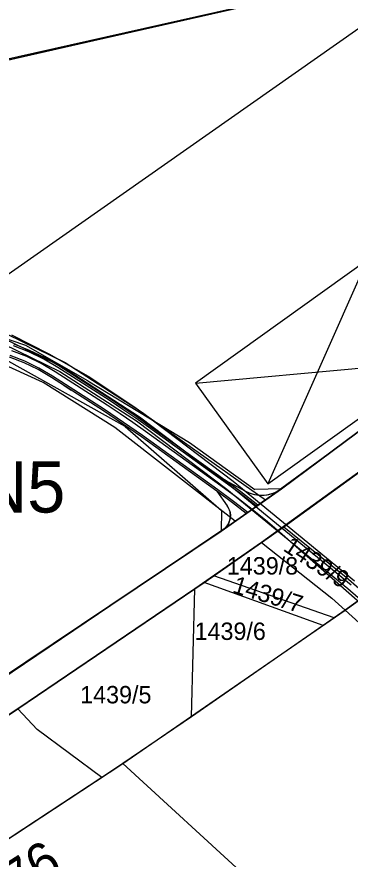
# Model space of a CAD drawing. Extents: x -510185 to -506993, y -1126306 to -1123642.
# Drawn here: x -508711.9 to -508614.4, y -1125228.7 to -1124982 of the extents above; entities that cross this region are included whole.
import ezdxf

# ---------------------------------------------------------------- set-up
doc = ezdxf.new("R2010")
doc.units = 0
for name, color, linetype in [('parcelni hranice', 7, 'Continuous'), ('popis cesty', 7, 'Continuous'), ('telefonica', 7, 'Continuous'), ('u_cesta20', 7, 'Continuous'), ('u_dalnice', 7, 'Continuous'), ('u_osa20', 7, 'Continuous'), ('u_popis', 7, 'Continuous'), ('u_stav dvur', 7, 'Continuous'), ('u_Telefonica', 7, 'Continuous'), ('u_vysadba', 7, 'Continuous'), ('ČEPS', 7, 'Continuous'), ('ˇ2', 7, 'Continuous')]:
    doc.layers.add(name, color=color, linetype=linetype)

msp = doc.modelspace()

# ---------------------------------------------------------------- linework, layer by layer
at = {"layer": 'parcelni hranice'}
for p, q in [((-508709.33, -1125078.25), (-508721.11, -1125074.28)), ((-508691.12, -1125088.59), (-508709.33, -1125078.25)), ((-508680.22, -1125102.02), (-508718.25, -1125080.76)), ((-508585.35, -1125083.77), (-508634.49, -1125120.22)), ((-508633.81, -1125131.37), (-508568.56, -1125084.09)), ((-508691.12, -1125088.59), (-508661.39, -1125106.67)), ((-508680.22, -1125102.02), (-508652.06, -1125126.63)), ((-508661.39, -1125106.67), (-508642.21, -1125120.44)), ((-508634.49, -1125120.22), (-508652.13, -1125132.63)), ((-508634.49, -1125120.22), (-508642.21, -1125120.44)), ((-508652.06, -1125126.63), (-508652.13, -1125132.63)), ((-508652.13, -1125132.63), (-508746.81, -1125196.18)), ((-508640.34, -1125135.94), (-508633.81, -1125131.37)), ((-508633.81, -1125131.37), (-508615.48, -1125146.13)), ((-508654.23, -1125145.68), (-508640.34, -1125135.94)), ((-508640.34, -1125135.94), (-508619.67, -1125152.26)), ((-508657.04, -1125147.63), (-508654.23, -1125145.68)), ((-508619.03, -1125158), (-508654.23, -1125145.68)), ((-508659.86, -1125149.57), (-508657.04, -1125147.63)), ((-508622.24, -1125160.26), (-508657.04, -1125147.63)), ((-508615.48, -1125146.13), (-508609.53, -1125151.29)), ((-508711.6, -1125184.7), (-508659.86, -1125149.57)), ((-508660.77, -1125187.02), (-508659.86, -1125149.57)), ((-508619.67, -1125152.26), (-508615.84, -1125155.75)), ((-508609.53, -1125151.29), (-508615.84, -1125155.75)), ((-508615.84, -1125155.75), (-508619.03, -1125158)), ((-508615.84, -1125155.75), (-508530.18, -1125233.9)), ((-508619.03, -1125158), (-508622.24, -1125160.26)), ((-508622.24, -1125160.26), (-508660.77, -1125187.02)), ((-508760.01, -1125216.39), (-508711.6, -1125184.7)), ((-508705.95, -1125190.73), (-508711.6, -1125184.7)), ((-508660.77, -1125187.02), (-508680.92, -1125200.66)), ((-508687.01, -1125204.78), (-508705.95, -1125190.73)), ((-508680.92, -1125200.66), (-508687.01, -1125204.78)), ((-508556.11, -1125315.05), (-508680.92, -1125200.66)), ((-508687.01, -1125204.78), (-508728.66, -1125232.15))]:
    msp.add_line(p, q, dxfattribs=at)
at = {"layer": 'telefonica'}
for points in [[(-508883.18, -1125073.45), (-508848.29, -1125060.66), (-508845.68, -1125060.26), (-508841.86, -1125061), (-508824.64, -1125072.31), (-508818.22, -1125076.69), (-508812.05, -1125079.64), (-508805.35, -1125080.64), (-508779.88, -1125079.41), (-508772.41, -1125078.59), (-508743.29, -1125072.5), (-508731.62, -1125071.61), (-508723.83, -1125072.19), (-508714.78, -1125074.96), (-508697.81, -1125083.24), (-508675.13, -1125097.89), (-508648.63, -1125118), (-508613.07, -1125147.17)], [(-508920.84, -1125089.73), (-508882.18, -1125076.27), (-508847.53, -1125063.58), (-508845.74, -1125063.3), (-508843.02, -1125063.84), (-508826.3, -1125074.81), (-508819.72, -1125079.29), (-508812.93, -1125082.54), (-508805.51, -1125083.66), (-508779.64, -1125082.41), (-508771.93, -1125081.55), (-508742.87, -1125075.48), (-508731.62, -1125074.61), (-508724.39, -1125075.15), (-508715.88, -1125077.76), (-508699.29, -1125085.86), (-508676.85, -1125100.35), (-508650.49, -1125120.36), (-508615.01, -1125149.47), (-508589.41, -1125171.82)]]:
    msp.add_lwpolyline(points, dxfattribs=at)
at = {"layer": 'u_cesta20'}
for p, q in [((-508698.1, -1125090), (-508696.04, -1125091.32)), ((-508650.98, -1125117.75), (-508645, -1125120.92)), ((-508653.35, -1125120.96), (-508650.32, -1125125.2))]:
    msp.add_line(p, q, dxfattribs=at)
for points in [[(-508641.78, -1125125.35), (-508646.65, -1125121.56), (-508651.29, -1125118.14), (-508673.43, -1125102.21), (-508677.13, -1125099.59), (-508680.86, -1125097.01), (-508684.63, -1125094.49), (-508688.43, -1125092.03), (-508699.92, -1125084.68), (-508704.06, -1125082.26), (-508708.4, -1125080.14), (-508712.88, -1125078.37)], [(-508641.35, -1125125.05), (-508646.35, -1125121.16), (-508651, -1125117.73), (-508673.14, -1125101.8), (-508676.84, -1125099.18), (-508680.58, -1125096.6), (-508684.36, -1125094.07), (-508688.16, -1125091.61), (-508699.66, -1125084.25), (-508703.82, -1125081.82), (-508708.2, -1125079.69), (-508712.72, -1125077.9)], [(-508644.77, -1125127.45), (-508648.77, -1125124.35), (-508653.35, -1125120.96), (-508675.47, -1125105.05), (-508679.13, -1125102.45), (-508682.83, -1125099.91), (-508686.56, -1125097.42), (-508690.33, -1125094.97), (-508701.75, -1125087.67), (-508705.71, -1125085.34), (-508709.81, -1125083.35), (-508714.04, -1125081.68)], [(-508644.34, -1125127.15), (-508648.47, -1125123.95), (-508653.06, -1125120.56), (-508675.18, -1125104.65), (-508678.85, -1125102.04), (-508682.55, -1125099.5), (-508686.28, -1125097), (-508690.06, -1125094.55), (-508701.49, -1125087.24), (-508705.48, -1125084.9), (-508709.61, -1125082.89), (-508713.88, -1125081.2)]]:
    msp.add_lwpolyline(points, dxfattribs=at)
for points in [[(-508650.98, -1125117.75), (-508645, -1125120.92), (-508643.93, -1125121.44), (-508642.78, -1125121.77), (-508641.46, -1125122.04), (-508640.41, -1125122.1), (-508639.56, -1125122.06), (-508638.64, -1125121.96), (-508637.53, -1125121.71), (-508636.32, -1125121.27), (-508635.46, -1125120.84), (-508634.49, -1125120.22), (-508641.35, -1125125.05), (-508646.35, -1125121.16)], [(-508653.35, -1125120.96), (-508650.32, -1125125.2), (-508649.54, -1125126.75), (-508649.38, -1125127.82), (-508649.46, -1125128.94), (-508649.92, -1125130.49), (-508650.61, -1125131.35), (-508651.51, -1125132.2), (-508644.77, -1125127.45), (-508648.77, -1125124.35)]]:
    msp.add_lwpolyline(points, close=True, dxfattribs=at)
for centre, radius, start, end in [((-508640.31, -1125112.09), 10, 242.0215, 306.5665), ((-508654.39, -1125128.11), 5, 305.127, 35.5821)]:
    msp.add_arc(centre, radius, start, end, dxfattribs=at)
at = {"layer": 'u_dalnice'}
for points in [[(-508307.98, -1124853.09), (-508351.15, -1124903.3), (-508395.31, -1124933.42), (-508430.84, -1124957.09), (-508470.01, -1124969.39), (-508498.1, -1124985.49), (-508504.09, -1124992.25), (-508507.8, -1125000.91), (-508507.87, -1125010.02), (-508504.83, -1125020.2), (-508497.14, -1125029.69), (-508568.56, -1125084.09), (-508640.34, -1125135.94), (-508659.86, -1125149.57), (-508711.6, -1125184.7), (-508760.01, -1125216.39), (-508781.13, -1125229.9), (-508797.28, -1125240.07), (-508802.36, -1125243.25), (-508808.34, -1125246.99), (-508884.57, -1125292.95)], [(-508883.7, -1125327.34), (-508849.68, -1125307.43), (-508793.17, -1125273.22), (-508768.24, -1125257.59), (-508728.66, -1125232.15), (-508680.92, -1125200.66), (-508615.84, -1125155.75), (-508609.53, -1125151.29), (-508577.81, -1125128.66), (-508544.87, -1125104.09), (-508479.09, -1125054.05), (-508464.05, -1125074.51), (-508457.81, -1125079.15), (-508450.36, -1125080.3), (-508443.41, -1125079.08), (-508435.52, -1125073.29), (-508420.42, -1125058.52), (-508416.68, -1125054.97), (-508374.92, -1125015.28), (-508354.65, -1124976.88), (-508350.21, -1124971.95), (-508276.53, -1124888.42)], [(-508560.91, -1124929.62), (-508567.97, -1124954.59), (-508793.68, -1125112.97), (-509052.14, -1125265.43), (-509087.92, -1125269.66)]]:
    msp.add_lwpolyline(points, dxfattribs=at)
at = {"layer": 'u_osa20'}
msp.add_lwpolyline([(-508527.62, -1125227.51), (-508634.24, -1125133.64), (-508638.59, -1125129.9), (-508643.03, -1125126.27), (-508647.56, -1125122.76), (-508652.17, -1125119.35), (-508674.3, -1125103.43), (-508677.99, -1125100.82), (-508681.71, -1125098.25), (-508685.46, -1125095.74), (-508689.25, -1125093.29), (-508700.71, -1125085.96), (-508704.77, -1125083.58), (-508709, -1125081.52), (-508713.38, -1125079.79)], dxfattribs=at)
at = {"layer": 'u_stav dvur'}
for p, q in [((-508609.4, -1125053.25), (-508638.47, -1125118.8)), ((-508659.65, -1125089.26), (-508588.23, -1125082.79))]:
    msp.add_line(p, q, dxfattribs=at)
msp.add_lwpolyline([(-508638.47, -1125118.8), (-508588.23, -1125082.79), (-508609.4, -1125053.25), (-508659.65, -1125089.26)], close=True, dxfattribs=at)
at = {"layer": 'u_Telefonica'}
msp.add_lwpolyline([(-508921.34, -1125088.32), (-508882.68, -1125074.86), (-508847.91, -1125062.12), (-508845.71, -1125061.78), (-508842.44, -1125062.42), (-508825.47, -1125073.56), (-508818.97, -1125077.99), (-508812.49, -1125081.09), (-508805.43, -1125082.15), (-508779.76, -1125080.91), (-508772.17, -1125080.07), (-508743.08, -1125073.99), (-508731.62, -1125073.11), (-508724.11, -1125073.67), (-508715.33, -1125076.36), (-508698.55, -1125084.55), (-508675.99, -1125099.12), (-508649.56, -1125119.18), (-508614.04, -1125148.32)], dxfattribs=at)
msp.add_lwpolyline([(-508921.34, -1125088.32), (-508882.68, -1125074.86), (-508847.91, -1125062.12), (-508845.71, -1125061.78), (-508842.44, -1125062.42), (-508825.47, -1125073.56), (-508818.97, -1125077.99), (-508812.49, -1125081.09), (-508805.43, -1125082.15), (-508779.76, -1125080.91), (-508772.17, -1125080.07), (-508743.08, -1125073.99), (-508731.62, -1125073.11), (-508724.11, -1125073.67), (-508715.33, -1125076.36), (-508698.55, -1125084.55), (-508675.99, -1125099.12), (-508649.56, -1125119.18), (-508614.04, -1125148.32)], dxfattribs=at)
msp.add_lwpolyline([(-508921.34, -1125088.32), (-508882.68, -1125074.86), (-508847.91, -1125062.12), (-508845.71, -1125061.78), (-508842.44, -1125062.42), (-508825.47, -1125073.56), (-508818.97, -1125077.99), (-508812.49, -1125081.09), (-508805.43, -1125082.15), (-508779.76, -1125080.91), (-508772.17, -1125080.07), (-508743.08, -1125073.99), (-508731.62, -1125073.11), (-508724.11, -1125073.67), (-508715.33, -1125076.36), (-508698.55, -1125084.55), (-508675.99, -1125099.12), (-508649.56, -1125119.18), (-508614.04, -1125148.32)], dxfattribs=at)
msp.add_lwpolyline([(-508921.34, -1125088.32), (-508882.68, -1125074.86), (-508847.91, -1125062.12), (-508845.71, -1125061.78), (-508842.44, -1125062.42), (-508825.47, -1125073.56), (-508818.97, -1125077.99), (-508812.49, -1125081.09), (-508805.43, -1125082.15), (-508779.76, -1125080.91), (-508772.17, -1125080.07), (-508743.08, -1125073.99), (-508731.62, -1125073.11), (-508724.11, -1125073.67), (-508715.33, -1125076.36), (-508698.55, -1125084.55), (-508675.99, -1125099.12), (-508649.56, -1125119.18), (-508614.04, -1125148.32)], dxfattribs=at)
at = {"layer": 'u_vysadba'}
for p, q in [((-508634.49, -1125120.22), (-508585.35, -1125083.77)), ((-508652.13, -1125132.63), (-508634.49, -1125120.22)), ((-508746.81, -1125196.18), (-508652.13, -1125132.63))]:
    msp.add_line(p, q, dxfattribs=at)
for points in [[(-508573.27, -1124905.18), (-508693.43, -1124932.21), (-508701.3, -1124937.12), (-508707.69, -1124938.84), (-508716.04, -1124937.62), (-508729.56, -1124953.83), (-508713.83, -1124975.46), (-508717.76, -1124995.36), (-508574.5, -1124962.68)], [(-508647.99, -1125129.69), (-508683.19, -1125102.31), (-508704.19, -1125089.14), (-508717.77, -1125082.96), (-508733.83, -1125080.08), (-508778.3, -1125085.43), (-508789, -1125094.28), (-508786.94, -1125098.81), (-508793.12, -1125121.25), (-508758.95, -1125135.66), (-508749.89, -1125150.27), (-508745.15, -1125170.24), (-508752.36, -1125189.8), (-508767.8, -1125207.91), (-508752.36, -1125197.83), (-508746.18, -1125195.97)]]:
    msp.add_lwpolyline(points, close=True, dxfattribs=at)
for points in [[(-508574.5, -1124962.95), (-508717.98, -1124995.47)], [(-508713.45, -1125075.14), (-508702.54, -1125080.7), (-508691.01, -1125087.28), (-508677.63, -1125096.14), (-508662.81, -1125106.63), (-508639.14, -1125123.51), (-508585.21, -1125083.78)]]:
    msp.add_lwpolyline(points, dxfattribs=at)
at = {"layer": 'ČEPS'}
msp.add_lwpolyline([(-510185.05, -1125367.76), (-510002.86, -1125297.71), (-509683.9, -1125222.3), (-509360.43, -1125146.6), (-509044.57, -1125071.75), (-508717.34, -1124994.86), (-508389.12, -1124921.16), (-508070.72, -1124848.1), (-507890, -1124804.52)], dxfattribs=at)

# ---------------------------------------------------------------- texts
at = {"layer": 'popis cesty'}
msp.add_text('KÚ-km 0,976', height=11, rotation=32.5947, dxfattribs=at).set_placement((-508770.35, -1125278.13))
at = {"layer": 'u_popis'}
msp.add_text('Nádrž N5', height=15, dxfattribs=at).set_placement((-508782.45, -1125127.19))
at = {"layer": 'ˇ2'}
for s, rotation, p in [('1439/9', 326.7005, (-508634.25, -1125138.18)), ('1439/7', 342.9152, (-508649.1, -1125150.52))]:
    msp.add_text(s, height=5.1, rotation=rotation, dxfattribs=at).set_placement(p)
for s, p in [('1439/8', (-508650.44, -1125145.34)), ('1439/6', (-508659.89, -1125164.5)), ('1439/5', (-508693.38, -1125183.08))]:
    msp.add_text(s, height=5.1, dxfattribs=at).set_placement(p)

doc.saveas('drawing.dxf')
